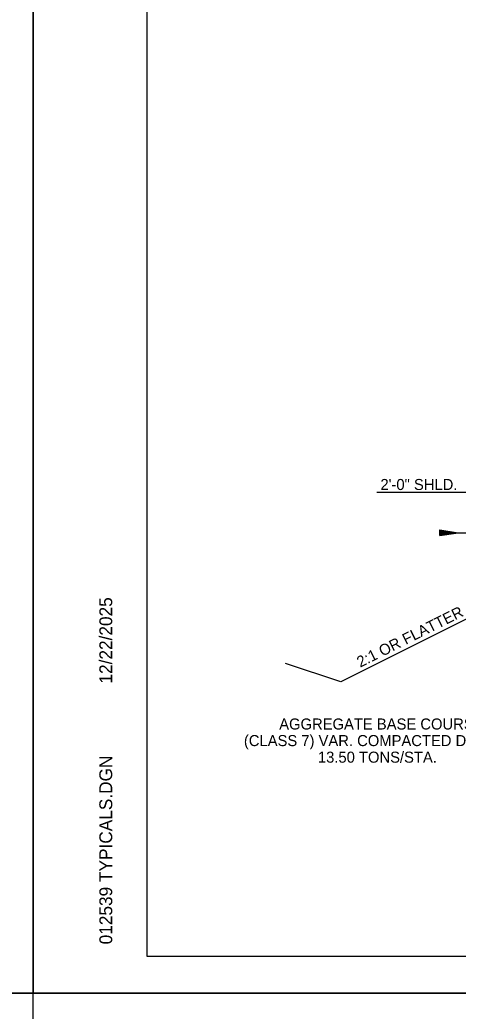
# Model space of a CAD drawing. Extents: x 2263886 to 2266026, y -3122850 to -3121850.
# Drawn here: x 2265358.3 to 2265382.1, y -3122444.8 to -3122391 of the extents above; entities that cross this region are included whole.
import ezdxf

# ---------------------------------------------------------------- set-up
doc = ezdxf.new("R2010")
doc.units = 0
for name, color, linetype in [('_CIVIL_CONSTRUCTION', 7, 'Continuous'), ('R_Border Notes', 7, 'Continuous'), ('R_Border Prem', 7, 'Continuous'), ('R_Draft', 7, 'Continuous')]:
    doc.layers.add(name, color=color, linetype=linetype)

msp = doc.modelspace()

# ---------------------------------------------------------------- linework, layer by layer
at = {"layer": '_CIVIL_CONSTRUCTION'}
for p, q in [((2265192.355, -3122443.817), (2265359.022, -3122443.817)), ((2265359.022, -3122443.82), (2265525.688, -3122443.82)), ((2265359.025, -3122443.817), (2265525.692, -3122443.817))]:
    msp.add_line(p, q, dxfattribs=at)
for points in [[(2265192.352, -3122337.151), (2265359.022, -3122337.151), (2265359.022, -3122443.82), (2265192.352, -3122443.82)], [(2265359.022, -3122337.151), (2265525.692, -3122337.151), (2265525.692, -3122443.82), (2265359.022, -3122443.82)], [(2265482.186, -3122339.098), (2265482.186, -3122344.038), (2265500.052, -3122344.038), (2265500.052, -3122345.498), (2265511.651, -3122345.498), (2265511.651, -3122357.664), (2265523.316, -3122357.664), (2265523.316, -3122441.828), (2265365.226, -3122441.828), (2265365.226, -3122339.098)], [(2265359.018, -3122443.82), (2265525.688, -3122443.82), (2265525.688, -3122550.488), (2265359.018, -3122550.488)]]:
    msp.add_lwpolyline(points, close=True, dxfattribs=at)
at = {"layer": 'R_Border Notes'}
for p, q in [((2265384.582, -3122422.497), (2265375.74, -3122426.918)), ((2265375.74, -3122426.918), (2265372.74, -3122425.918))]:
    msp.add_line(p, q, dxfattribs=at)
at = {"layer": 'R_Border Prem'}
for p, q in [((2265386.579, -3122416.627), (2265377.694, -3122416.627)), ((2265381.118, -3122418.668), (2265382.118, -3122418.818)), ((2265381.118, -3122418.968), (2265381.118, -3122418.668)), ((2265381.118, -3122418.693), (2265381.951, -3122418.818)), ((2265381.118, -3122418.718), (2265381.779, -3122418.818)), ((2265381.118, -3122418.743), (2265381.612, -3122418.818)), ((2265381.118, -3122418.769), (2265381.443, -3122418.818)), ((2265381.118, -3122418.794), (2265381.276, -3122418.818)), ((2265381.118, -3122418.968), (2265382.118, -3122418.818)), ((2265381.118, -3122418.866), (2265381.443, -3122418.818)), ((2265381.118, -3122418.917), (2265381.779, -3122418.818)), ((2265381.118, -3122418.943), (2265381.951, -3122418.818)), ((2265381.118, -3122418.892), (2265381.612, -3122418.818)), ((2265381.118, -3122418.841), (2265381.276, -3122418.818)), ((2265382.118, -3122418.818), (2265384.513, -3122418.818))]:
    msp.add_line(p, q, dxfattribs=at)
at = {"layer": 'R_Draft'}
for p, q in [((2265365.226, -3122441.828), (2265365.226, -3122339.098)), ((2265365.226, -3122441.828), (2265365.226, -3122441.828)), ((2265523.316, -3122441.828), (2265365.226, -3122441.828))]:
    msp.add_line(p, q, dxfattribs=at)

# ---------------------------------------------------------------- texts
at = {"layer": 'R_Border Prem'}
for s, p in [('2\'-0" SHLD.', (2265377.894, -3122416.499)), ('AGGREGATE BASE COURSE', (2265372.394, -3122429.503)), ('(CLASS 7) VAR. COMPACTED DEPTH', (2265370.476, -3122430.403)), ('13.50 TONS/STA.', (2265374.497, -3122431.303))]:
    msp.add_text(s, height=0.6, dxfattribs=at).set_placement(p)
msp.add_text('2:1 OR FLATTER', height=0.6, rotation=26.565, dxfattribs=at).set_placement((2265376.799, -3122426.148))
at = {"layer": 'R_Draft'}
for s, p in [('12/22/2025', (2265363.321, -3122427.007)), ('012539 TYPICALS.DGN', (2265363.321, -3122441.166))]:
    msp.add_text(s, height=0.7, rotation=90, dxfattribs=at).set_placement(p)

doc.saveas('drawing.dxf')
